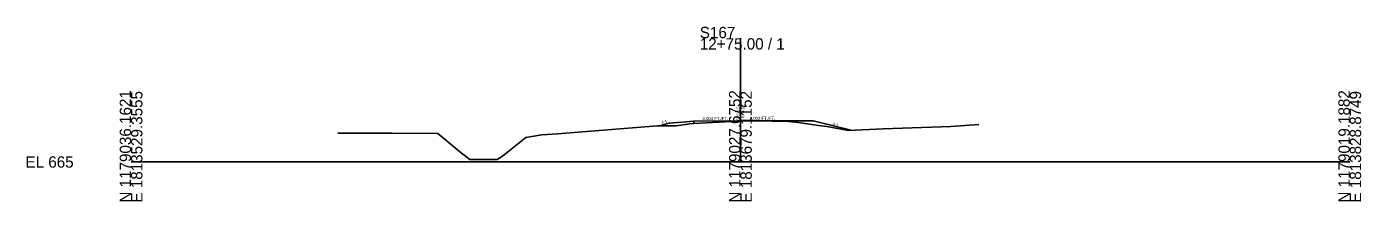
# Model space of a CAD drawing. Extents: x -26 to 6803, y -10 to 1023.
# Drawn here: x 3874.3 to 4202.8, y -9.7 to 33.3 of the extents above; entities that cross this region are included whole.
import ezdxf

# ---------------------------------------------------------------- set-up
doc = ezdxf.new("R2010")
doc.units = 0
for name, color, linetype in [('Default', 7, 'Continuous'), ('RD_GPK_XS_Cell', 7, 'Continuous'), ('RD_XS_EarthShd', 7, 'Continuous'), ('RD_XS_ExGround', 7, 'Continuous'), ('RD_XS_Misc_Line', 7, 'Continuous'), ('RD_XS_Pave', 7, 'Continuous'), ('RD_XS_TieSlope', 7, 'Continuous'), ('RD_XS_TX_Elev_EX', 7, 'Continuous'), ('RD_XS_TX_Elev_PR', 7, 'Continuous'), ('RD_XS_TX_Slope', 7, 'Continuous')]:
    doc.layers.add(name, color=color, linetype=linetype)

msp = doc.modelspace()

# ---------------------------------------------------------------- linework, layer by layer
at = {"layer": 'Default'}
for p, q in [((4038.52, 10.07), (4050, 10.12)), ((4050, 10.12), (4061.87, 10.14))]:
    msp.add_line(p, q, dxfattribs=at)
at = {"layer": 'RD_GPK_XS_Cell'}
for p, q in [((4050, 0), (4050, 30.49)), ((3900, 0), (4050, 0)), ((4050, 0), (4200, 0))]:
    msp.add_line(p, q, dxfattribs=at)
at = {"layer": 'RD_XS_EarthShd'}
for p, q in [((4038.52, 10.07), (4032.52, 9.57)), ((4061.87, 10.14), (4067.87, 10.15))]:
    msp.add_line(p, q, dxfattribs=at)
at = {"layer": 'RD_XS_ExGround'}
msp.add_lwpolyline([(3950.93, 7.12), (3964.18, 7.11), (3975.5, 7.03), (3981.3, 2.14), (3983.41, 0.61), (3984.05, 0.61), (3987.19, 0.6), (3989.65, 0.62), (3990.1, 0.62), (3991.41, 1.46), (3997.14, 6.02), (4001.12, 6.66), (4004.95, 6.92), (4029.62, 8.94), (4034.2, 8.94), (4037.56, 9.36), (4038.52, 9.51), (4047.71, 10), (4050, 10.12), (4050.85, 10.16), (4053.57, 10.11), (4061.87, 9.96), (4062.58, 9.88), (4064.21, 9.69), (4069.22, 8.95), (4071.24, 8.78), (4075.26, 7.97), (4076.52, 7.76), (4085.13, 8.19), (4101.8, 8.78), (4108.71, 9.23)], dxfattribs=at)
at = {"layer": 'RD_XS_Misc_Line'}
for points in [[(4037.56, 9.36), (4038.52, 9.51), (4038.52, 10.07), (4032.52, 9.57), (4030.02, 8.94), (4034.2, 8.94)], [(4037.56, 9.36), (4038.52, 9.51), (4038.52, 10.07), (4032.52, 9.57), (4030.02, 8.94), (4034.2, 8.94)], [(4037.56, 9.36), (4038.52, 9.51), (4038.52, 10.07), (4032.52, 9.57), (4030.02, 8.94), (4034.2, 8.94)], [(4038.52, 10.07), (4038.52, 9.51), (4037.56, 9.36), (4034.2, 8.94), (4030.02, 8.94), (4032.52, 9.57)], [(4038.52, 10.07), (4038.52, 9.51), (4037.56, 9.36), (4034.2, 8.94), (4030.02, 8.94), (4032.52, 9.57)], [(4047.71, 10), (4050, 10.12), (4038.52, 10.07), (4038.52, 9.51)], [(4047.71, 10), (4050, 10.12), (4038.52, 10.07), (4038.52, 9.51)], [(4047.71, 10), (4050, 10.12), (4038.52, 10.07), (4038.52, 9.51)], [(4038.52, 10.07), (4038.52, 9.51), (4047.71, 10), (4050, 10.12)], [(4038.52, 10.07), (4038.52, 9.51), (4047.71, 10), (4050, 10.12)], [(4050, 10.12), (4050.85, 10.16), (4052.79, 10.12)], [(4050, 10.12), (4050.85, 10.16), (4052.79, 10.12)], [(4050, 10.12), (4050.85, 10.16), (4052.79, 10.12)], [(4050.85, 10.16), (4052.79, 10.12), (4050, 10.12)], [(4050.85, 10.16), (4052.79, 10.12), (4050, 10.12)], [(4052.79, 10.12), (4061.87, 10.14), (4061.87, 9.96), (4053.57, 10.11)], [(4052.79, 10.12), (4061.87, 10.14), (4061.87, 9.96), (4053.57, 10.11)], [(4052.79, 10.12), (4061.87, 10.14), (4061.87, 9.96), (4053.57, 10.11)], [(4052.79, 10.12), (4053.57, 10.11), (4061.87, 9.96), (4061.87, 10.14)], [(4052.79, 10.12), (4053.57, 10.11), (4061.87, 9.96), (4061.87, 10.14)], [(4075.26, 7.97), (4076.52, 7.76), (4077.26, 7.8), (4067.87, 10.15), (4061.87, 10.14), (4061.87, 9.96), (4062.58, 9.88), (4064.21, 9.69), (4069.22, 8.95), (4071.24, 8.78)], [(4075.26, 7.97), (4076.52, 7.76), (4077.26, 7.8), (4067.87, 10.15), (4061.87, 10.14), (4061.87, 9.96), (4062.58, 9.88), (4064.21, 9.69), (4069.22, 8.95), (4071.24, 8.78)], [(4075.26, 7.97), (4076.52, 7.76), (4077.26, 7.8), (4067.87, 10.15), (4061.87, 10.14), (4061.87, 9.96), (4062.58, 9.88), (4064.21, 9.69), (4069.22, 8.95), (4071.24, 8.78)], [(4061.87, 9.96), (4062.58, 9.88), (4064.21, 9.69), (4069.22, 8.95), (4071.24, 8.78), (4075.26, 7.97), (4076.52, 7.76), (4077.26, 7.8), (4067.87, 10.15), (4061.87, 10.14)], [(4061.87, 9.96), (4062.58, 9.88), (4064.21, 9.69), (4069.22, 8.95), (4071.24, 8.78), (4075.26, 7.97), (4076.52, 7.76), (4077.26, 7.8), (4067.87, 10.15), (4061.87, 10.14)]]:
    msp.add_lwpolyline(points, close=True, dxfattribs=at)
at = {"layer": 'RD_XS_Pave'}
for p, q in [((4038.52, 10.07), (4038.52, 9.51)), ((4061.87, 9.96), (4061.87, 10.14))]:
    msp.add_line(p, q, dxfattribs=at)
at = {"layer": 'RD_XS_TieSlope'}
for p, q in [((4067.87, 10.15), (4077.26, 7.8)), ((4032.52, 9.57), (4030.02, 8.94))]:
    msp.add_line(p, q, dxfattribs=at)

# ---------------------------------------------------------------- texts
at = {"layer": 'RD_GPK_XS_Cell'}
for s, p in [('S167', (4040, 30.49)), ('12+75.00 / 1', (4040, 27.69)), ('EL 665', (3874, -1.4))]:
    msp.add_text(s, height=2.8, dxfattribs=at).set_placement(p)
for s, p in [('N 1179036.1621', (3900, -10)), ('E 1813529.3555', (3902.8, -10)), ('N 1179027.6752', (4050, -10)), ('E 1813679.1152', (4052.8, -10)), ('N 1179019.1882', (4200, -10)), ('E 1813828.8749', (4202.8, -10))]:
    msp.add_text(s, height=2.8, rotation=90, dxfattribs=at).set_placement(p)
at = {"layer": 'RD_XS_TX_Elev_EX'}
msp.add_text('675.12', height=0.8, rotation=90, dxfattribs=at).set_placement((4049.86, 10.18))
at = {"layer": 'RD_XS_TX_Elev_PR'}
msp.add_text('675.12', height=0.8, rotation=90, dxfattribs=at).set_placement((4050.93, 10.82))
at = {"layer": 'RD_XS_TX_Slope'}
for s, rotation, p in [('4:1', 14.0362, (4030.64, 9.32)), ('0.004 FT./FT.', 0.2521, (4040.69, 10.33)), ('0.002 FT./FT.', 0.0917, (4052.3, 10.37)), ('4:1', 345.9638, (4072.6, 9.03))]:
    msp.add_text(s, height=0.75, rotation=rotation, dxfattribs=at).set_placement(p)

doc.saveas('drawing.dxf')
